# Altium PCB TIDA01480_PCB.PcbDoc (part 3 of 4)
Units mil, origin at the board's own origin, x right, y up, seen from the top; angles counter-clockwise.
Board outline 2500 x 3500 mil, 6 copper layers (Top Layer, GND Upper, Signal Layer 1, Signal Layer 2, GND Lower, Bottom Layer), stack 63.4 mil thick; 332 components, 140 nets, 983 pads, 692 vias.
Unrouted connection lines stored in the file: 17.
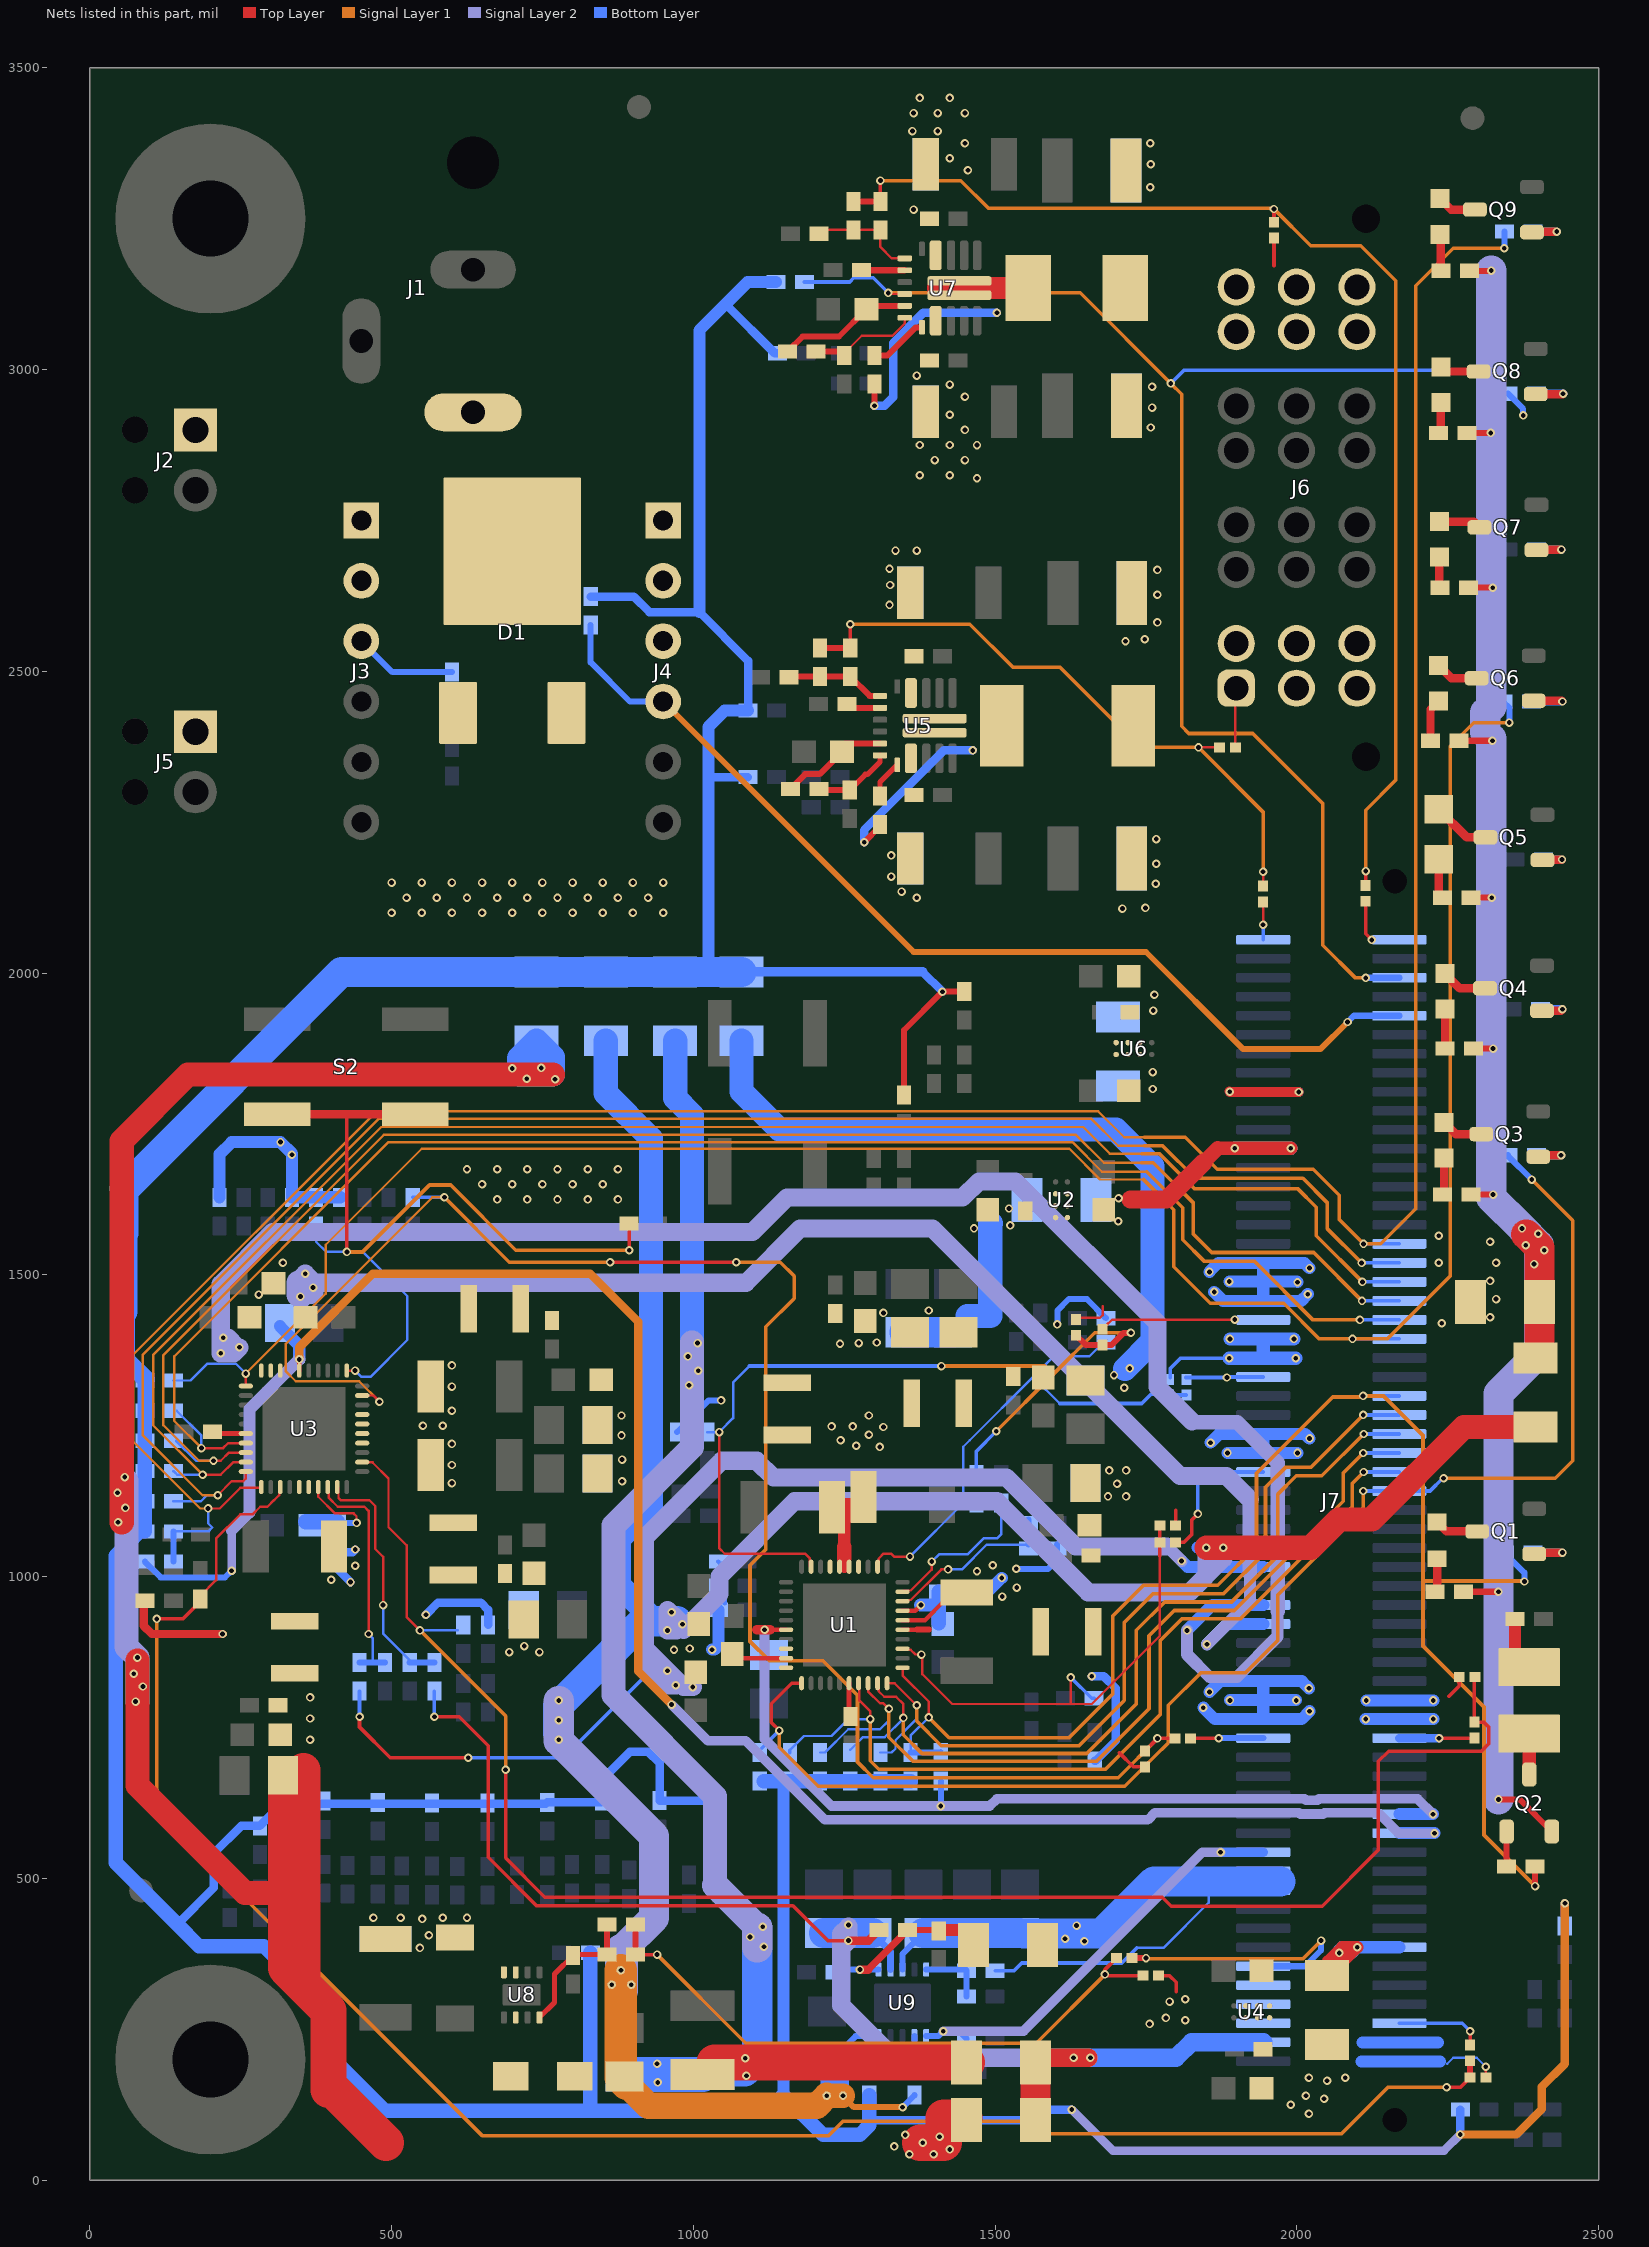
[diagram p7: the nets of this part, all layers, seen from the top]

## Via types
v1: diameter 14, hole 7.9, Top Layer to Bottom Layer, tented both sides, 676 vias
v2: diameter 19.68, hole 7.87, Top Layer to Bottom Layer, 16 vias

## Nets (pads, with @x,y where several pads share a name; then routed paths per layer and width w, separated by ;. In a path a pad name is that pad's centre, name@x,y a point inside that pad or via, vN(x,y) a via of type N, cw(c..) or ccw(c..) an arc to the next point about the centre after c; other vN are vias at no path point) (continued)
HOT_RESETz_B: R29.1 R38.1 S2.3 S2.4 U3.11 | length 1475
  Top Layer w4: U3.11@425.87,1341.46 v1(439.54,1341.46)
  Top Layer w6: v1(426,1538) 426,1765.26 ; v1(894,1541) R29.1@894,1584.38
  Top Layer w14: S2.3@310.83,1766.26 S2.4@539.17,1766.26
  Signal Layer 1 w6: v1(426,1538) 452,1538 563,1649 598,1649 706,1541 v1(894,1541)
  Bottom Layer w4: R38.1@375,1581.38 375,1555 392,1538 v1(426,1538) 453,1538 526,1465 526,1392.14 464.86,1331 450,1331 v1(439.54,1341.46)
HV_AIC_PG: J4.4 J7.112 R156.2 | length 1689.6
  Signal Layer 1 w10: J4.4@950,2450 1365,2035 1750,2035 1911,1874 2039,1874 v1(2084,1919)
  Bottom Layer w10: R156.2@829.92,2576.38 829.92,2515 894.92,2450 J4.4@950,2450 ; v1(2084,1919) 2094.33,1929.33 J7.112@2169.74,1929.33
I2C_CLK_A: J7.70 R3.1 U1.30 | length 1386.1
  Top Layer w4: U1.30@1321.08,823.54 1333.46,823.54 v1(1370,787)
  Signal Layer 1 w6: v1(1370,787) 1370,761 1411,720 1639,720 1714,795 1714,924 1762,972 1879,972 1948,1041 1948,1148 1981,1181 2023.17,1181 v1(2110.09,1267.91)
  Bottom Layer w4: R3.1@1310,708.62 1328.62,708.62 1335,715 1335,729 1370,764 v1(1370,787)
  Bottom Layer w6: v1(2110.09,1267.91) J7.70@2169.74,1267.91
I2C_CLK_B: J7.86 R31.1 U3.30 | length 2813.2
  Top Layer w4: v1(212,1135) 235,1158 254,1158 258.54,1162.54 U3.30@258.54,1174.13
  Signal Layer 1 w4: v1(212,1135) 187,1135 88,1234 88,1368 479,1759 1659,1759 1704,1714 1747,1714
  Signal Layer 1 w6: 1747,1714 1777.38,1714 1831.38,1660 2010,1660 2050,1620 2050,1577 v1(2107.12,1519.88)
  Bottom Layer w4: R31.1@138.62,1125 184.14,1125 193.57,1134.43 v1@211.43,1134.43
  Bottom Layer w6: v1(2107.12,1519.88) J7.86@2169.74,1519.88
I2C_DAT_A: J7.68 R4.1 U1.29 | length 1409.2
  Top Layer w4: U1.29@1305.33,823.54 1307,821.88 1307,810.22 1316.22,801 1336,801 1348,789 v1(1348,766)
  Signal Layer 1 w6: v1(1348,766) 1348,738 1379,707 1652,707 1734,789 1734,911 1781,958 1891.62,958 1968,1034.38 1968,1136 1999,1167 2041.17,1167 v1(2110.58,1236.42)
  Bottom Layer w4: R4.1@1260,713 1281.24,734.24 1317.24,734.24 v1@1348,765
  Bottom Layer w6: v1(2110.58,1236.42) J7.68@2169.74,1236.42
I2C_DAT_B: J7.84 R32.1 U3.29 | length 2717.3
  Top Layer w4: v1(187,1169) 217,1169 237.88,1189.88 U3.29@258.54,1189.88
  Signal Layer 1 w4: v1(187,1169) 105,1251 105,1367 483,1745 1646,1745 1690,1701 1743,1701
  Signal Layer 1 w6: 1743,1701 1772,1701 1830,1643 2001,1643 2032,1612 2032,1565 v1(2108.61,1488.39)
  Bottom Layer w4: R32.1@138.62,1175 R32.1@142.62,1171 ; R32.1@144.62,1169 v1(187,1169) v1@187,1171
  Bottom Layer w6: v1(2108.61,1488.39) J7.84@2169.74,1488.39
INTERRUPTz_A: J7.66 R14.1 U1.28 | length 1433.5
  Top Layer w4: U1.28@1289.59,823.54 1289.59,810 1309.59,790 1315,790 v1(1324,781)
  Signal Layer 1 w6: v1(1324,781) 1324,734 1364,694 1668,694 1755,781 1755,902 1797,944 1896,944 2077,1125 2077,1171.84 v1(2110.08,1204.92)
  Bottom Layer w4: R14.1@1210,708.62 1218.28,708.62 1256.78,747.13 1309.13,747.13 1324,762 v1@1324,780.13
  Bottom Layer w6: v1(2110.08,1204.92) J7.66@2169.74,1204.92
INTERRUPTz_B: J7.82 R47.1 U3.28 | length 2701.6
  Top Layer w4: v1(205,1192) 217,1192 230.63,1205.63 U3.28@258.54,1205.63
  Signal Layer 1 w4: v1(205,1192) 181,1192 122,1251 122,1367 487,1732 1634,1732 1680,1686 1742,1686
  Signal Layer 1 w6: 1742,1686 1762,1686 1828,1620 1828,1568 1859,1537 2027.78,1537 v1(2107.89,1456.89)
  Bottom Layer w4: R47.1@143,1225 176,1192 v1(205,1192)
  Bottom Layer w6: v1(2107.89,1456.89) J7.82@2169.74,1456.89
LDO1B__or__VPS_MTRAVTT: C48.1 J7.49 U3.20 | length 2925
  Signal Layer 2 w20: v1(1818,911) 1818,871 1855,834 1901,834 1968,901 1968,943
  Signal Layer 2 w24: 1826,1257 1826.87,1256.13 1900.87,1256.13 1968,1189 1968,943
  Signal Layer 2 w30: v1(221,1396) 229,1396 245,1380 v1(248,1380) 238,1370 v1(217,1370) 217,1485 302.87,1570.87 1097.87,1570.87 1155,1628 1446,1628 1473,1655 1534,1655 1769,1420 1769,1314 1826,1257
  Bottom Layer w20: v1(1818,911) 1859.95,952.95 J7.49@1944.26,952.95
LDO2B: C49.1 J7.47 U3.18 | length 2266
  Signal Layer 2 w20: v1(1851,888) 1922,959 1922,1005
  Signal Layer 2 w24: 1922,1005 1922,1128
  Signal Layer 2 w30: 346,1491 v1(357,1502) 372,1487 ; 352,1487 372,1487 ; 386,1487 372,1487 ; 1922,1128 1883.13,1166.87 1806.13,1166.87 1396,1577 1177,1577 1087,1487 372,1487
  Signal Layer 2 w40: 346,1487 346,1467 v1(349,1464) ; 352,1487 367,1472
  Bottom Layer w20: v1(1851,888) 1884.46,921.46 J7.47@1944.26,921.46
  other v1: 370,1479
LOW_BATz_A: J7.62 R12.1 R125.1 U1.21 | length 2406
  Top Layer w6: v1@1143,744.5 1129,758.5 1129,789.41 1163.13,823.54 U1.21@1179.35,823.54
  Signal Layer 1 w6: v1(1142.5,745) 1142.5,717.5 1207,653 1715,653 1776.13,714.13 1776.41,714.13 1786.88,724.6 1786.88,786.88 1841,841 1915,841 1968,894 1968,969 2110.07,1111.07 v1(2110.07,1141.93) ; v1(2243,1163) 2428,1163 2457,1192 2457,1590 v1(2389,1658)
  Bottom Layer w6: R12.1@1110,708.62 1110,712.5 v1(1142.5,745) ; v1(2110.07,1141.93) J7.62@2169.74,1141.93 2220.64,1141.93 2241.72,1163 v1(2243,1163)
  Bottom Layer w10: R125.1@2350.14,1698.21 2350.14,1696.86 v1(2389,1658)
LOW_BATz_B: J7.78 R45.1 R128.1 U3.21 | length 3694.4
  Top Layer w4: U3.21@258.54,1315.87 v1(258.54,1336.46)
  Signal Layer 1 w4: v1(258.54,1336.46) 391,1468.91 391,1550 550,1709 1623,1709 1674,1658 1746,1658
  Signal Layer 1 w6: 1746,1658 1796,1608 1796,1513.49 1856.49,1453 1978,1453 2037.1,1393.9 v1(2092.1,1393.9) 2149.9,1393.9 2254,1498 2254,2376 2293,2415 v1(2352,2415)
  Bottom Layer w4: R45.1@138.62,1325 167.14,1325 195.14,1353 242,1353 v1(258.54,1336.46)
  Bottom Layer w6: v1(2092.1,1393.9) J7.78@2169.74,1393.9
  Bottom Layer w10: R128.1@2341.38,2450 2352,2439.38 v1(2352,2415)
LOWBAT_SNS_A: R7.1 R9.2 U1.39 | length 303.7
  Top Layer w4: U1.39@1346.67,975.12 1348.61,977.05 1360.27,977.05 1395,1011.79 v1(1395,1025)
  Bottom Layer w4: v1(1395,1025) 1407,1037 1454.44,1037 1481.44,1064 1504,1064 1510,1070 R9.2@1510,1122.38
  Bottom Layer w10: R7.1@1469,1122.38 R9.2@1510,1122.38
LOWBAT_SNS_B: R34.1 R35.2 U3.39 | length 405.1
  Top Layer w4: U3.39@410.12,1148.54 412.06,1146.61 412.06,1130.34 415.53,1126.86 463.14,1126.86 473,1117 473,1046 486,1033 v1(486,953)
  Bottom Layer w4: v1(486,953) 486,906 R35.2@530,862
  Bottom Layer w10: R35.2@530,857.62 R34.1@571,857.62
MidCurrent_PG: J7.116 R72.2 R133.1 U7.16 | length 2591.6
  Top Layer w4: v1@1320,3130 v1(1323,3127) 1324.84,3125.16 U7.16@1350.26,3125.16
  Signal Layer 1 w6: v1(1323,3127) 1641,3127 v1(1791,2977) 1809,2959 1809,2409 1821,2397 1927,2397 2043,2281 2043,2046 2097,1992 v1(2114,1992)
  Bottom Layer w6: R72.2@1183.84,3145 1259,3145 1265.87,3151.87 1298.13,3151.87 v1(1323,3127) ; v1(1791,2977) 1813,2999 2307,2999 2346,2960 R133.1@2350,2960
  Bottom Layer w10: v1@2114.32,1992.32 J7.116@2169.74,1992.32 ; R133.1@2350,2960 2375,2935 v1(2375,2924)
NetC7_1: C7.1 R1.2 U1.37 | length 113.7
  Top Layer w7: U1.37@1346.67,943.62 1367.62,943.62 v1(1377,953)
  Bottom Layer w22: v1(1377,953) 1404.4,953
  Bottom Layer w24: C7.1@1406.38,922.87 R1.2@1406.38,975
NetC22_1: C22.1 U1.26 | length 52.8
  Top Layer w7.8: C22.1@1258.09,770.75 U1.26@1258.09,823.54
NetC32_1: C32.1 R30.2 U3.37 | length 177.4
  Top Layer w4: U3.37@378.62,1148.54 378.62,1132.47 406.23,1104.86 437.14,1104.86 442,1100 v1(442,1089)
  Bottom Layer w10: R30.2@420,1089 v1(442,1089)
  Bottom Layer w26: C32.1@358,1091 R30.2@409.51,1091
NetC47_1: C47.1 U3.26 | length 52
  Top Layer w7.8: C47.1@206.5,1237.13 U3.26@258.54,1237.13
NetC51_1: C51.1 U5.1 | length 63.3
  Top Layer w9: C51.1@1309.27,2293.62 1309.27,2316.46 U5.1@1337.85,2345.04
NetC51_2: C51.2 L7.1 U5.6 U5.7 | length 291.8
  Top Layer w10: v1(1283,2217) C51.2@1309.27,2243.27
  Bottom Layer w14: v1(1283,2217) 1283,2237 1415,2369 v1(1463,2369)
NetC62_2: C62.2 R61.1 R63.2 U5.13 | length 162.6
  Top Layer w10: R63.2@1160,2491.38 C62.2@1210,2491.38 R61.1@1260,2491.38 1292.17,2459.21 U5.13@1309.31,2459.21
NetC67_1: C67.1 U5.14 | length 41.2
  Top Layer w10: C67.1@1268.15,2439.53 U5.14@1309.31,2439.53
NetC68_1: C68.1 U7.1 | length 97.9
  Top Layer w10: C68.1@1300,3023.62 1321.88,3023.62 1368.29,3070.04 U7.1@1378.72,3070.04
NetC68_2: C68.2 L8.1 U7.6 U7.7 | length 505.7
  Top Layer w10: v1(1300,2940) C68.2@1300,2976.38
  Top Layer w36: 1405,3135 L8.1@1554.78,3135
  Bottom Layer w14: v1(1300,2940) 1317,2940 1331,2954 1331,3044 1381,3094 v1(1503,3094)
NetC79_2: C79.2 R73.1 R74.2 U7.13 | length 171.4
  Top Layer w4: R74.2@1215,3231.38 C79.2@1265.22,3231.38 R73.1@1310,3231.38 1310,3203 1328.79,3184.21 U7.13@1350.26,3184.21
NetC81_1: C81.1 U7.14 | length 70.9
  Top Layer w10: C81.1@1279.31,3164.53 U7.14@1350.26,3164.53
NetC93_2: C93.2 R83.2 R86.2 U8.4 | length 232.8
  Top Layer w8: U8.4@745.16,269.69 770,294.53 770,341.71 R86.2@800.79,372.5 802.17,373.87 R83.2@857.17,373.87
  Top Layer w10: R83.2@857.17,373.87 C93.2@857.17,423.87
NetC94_1: C94.1 R81.1 U9.5 | length 108.1
  Bottom Layer w10: U9.5@1385.85,349.02 R81.1@1451.1,349.02 ; C94.1@1452.85,304.45 R81.1@1452.85,347.26
NetD1_1: D1.1 D1.3 J4.1 J4.2 J4.3
NetD2_1: D2.1 Q1.3 | length 72.8
  Top Layer w14: D2.1@2232.4,1090.51 2247.91,1075 Q1.3@2298.74,1075
NetD2_2: D2.2 R117.1 | length 50.9
  Top Layer w14: R117.1@2232.4,978.62 D2.2@2232.4,1029.49
NetD3_1: D3.1 Q2.3 | length 67.6
  Top Layer w23: Q2.3@2385,672.24 D3.1@2385,739.88
NetD3_2: D3.2 R118.2 | length 56.3
  Top Layer w20: D3.2@2361.38,873.74 R118.2@2361.38,930
NetD4_1: D4.1 R119.1 | length 58.3
  Top Layer w14: R119.1@2243.76,1635.38 D4.1@2243.76,1693.68
NetD4_2: D4.2 Q3.3 | length 69.7
  Top Layer w14: D4.2@2243.76,1752.74 2263.29,1733.21 Q3.3@2305.41,1733.21
NetD5_1: D5.1 R120.1 | length 65.1
  Top Layer w14: R120.1@2245.38,1875 D5.1@2245.38,1940.09
NetD5_2: D5.2 Q4.3 | length 76.8
  Top Layer w14: D5.2@2245,1999.53 2269.53,1975 Q4.3@2311.65,1975
NetD6_1: D6.1 R121.1 | length 57.3
  Top Layer w14: R121.1@2235,2131.38 D6.1@2235,2188.66
NetD6_2: D6.2 Q5.3 | length 96.6
  Top Layer w14: D6.2@2235,2271.34 2281.34,2225 Q5.3@2312.44,2225
NetD7_1: D7.1 R122.1 | length 71.1
  Top Layer w14: R122.1@2221.38,2385 2221.38,2436.85 D7.1@2235,2450.47
NetD7_2: D7.2 Q6.3 | length 71.4
  Top Layer w14: D7.2@2235,2509.53 2255.93,2488.6 Q6.3@2297.76,2488.6
NetD8_1: D8.1 R129.1 | length 49.1
  Top Layer w14: R129.1@2236.04,2639.96 D8.1@2236.04,2689.05
NetD8_2: D8.2 Q7.3 | length 70.4
  Top Layer w14: D8.2@2236.04,2748.11 2292.97,2748.11 Q7.3@2302.5,2738.58
NetD9_1: D9.1 R130.1 | length 46.9
  Top Layer w14: R130.1@2238.62,2898.62 D9.1@2238.62,2945.47
NetD9_2: D9.2 Q8.3 | length 65.6
  Top Layer w14: D9.2@2238.62,3004.53 2246.36,2996.79 Q8.3@2301.06,2996.79
NetD10_1: D10.1 R131.1 | length 59.1
  Top Layer w14: R131.1@2238.62,3163.52 D10.1@2238.62,3222.62
NetD10_2: D10.2 Q9.3 | length 65.2
  Top Layer w14: D10.2@2237.24,3283.05 2255.3,3265 Q9.3@2295,3265
NetJ3_1: J3.1 J3.2 J3.3 J5.1 R155.1 | length 171.3
  Bottom Layer w10: J3.3@450,2550 501.38,2498.62 R155.1@600,2498.62
NetJ7_6: J7.6 R153.1 | length 145.7
  Top Layer w6: R153.1@2287,223.99 v1(2287,247)
  Bottom Layer w6: J7.6@2169.74,260.04 2273.96,260.04 v1(2287,247)
NetJ7_11: J7.11 R151.2 | length 447.2
  Top Layer w10: R151.2@1726.99,368 v1(1750,368)
  Signal Layer 1 w6: v1@1750.87,367.13 2010.13,367.13 v1(2040,397)
  Bottom Layer w10: J7.11@1944.26,354.53 2013.53,354.53 2040,381 v1(2040,397)
NetJ7_35: J7.35 R148.2 | length 119.8
  Top Layer w6: R148.2@1824.47,732.48 v1(1870.52,732.48)
  Bottom Layer w10: v1(1870.52,732.48) J7.35@1944.26,732.48
NetJ7_36: J7.36 R149.1 | length 123.7
  Top Layer w6: v1(2235.52,732.48) R149.1@2293.47,732.48
  Bottom Layer w14: J7.36@2169.74,732.48 v1(2235.52,732.48)
NetJ7_63: J7.63 R144.2 | length 238.7
  Top Layer w6: R144.2@1798.99,1057 1813,1057 1825.92,1069.92 1825.92,1093.92 v1(1836,1104)
  Bottom Layer w6: v1(1836,1104) 1836,1157.25 1852.18,1173.43 J7.63@1944.26,1173.43
NetJ7_73: J7.73 R142.2 | length 127.4
  Bottom Layer w6: R142.2@1815.99,1330 v1(1884,1330) ; v1@1884.91,1330.91 J7.73@1944.26,1330.91
NetJ7_79: J7.79 R140.2 | length 217.1
  Top Layer w4: R140.2@1684.01,1416 1694.01,1426 v1(1897,1426)
NetJ7_119: J7.119 R137.2 | length 62.4
  Top Layer w4: v1(1944,2080) R137.2@1944,2118.01
  Bottom Layer w6: J7.119@1944,2055.58 v1(1944,2080)
NetJ7_120: J7.120 R138.1 | length 68.2
  Top Layer w6: R138.1@2114,2119.01 2114,2065 v1(2124,2055)
NetL1_1: L1.1 U1.7
NetL2_1: L2.1 U1.35 | length 43.4
  Top Layer w7: U1.35@1346.67,912.13 1370.87,912.13
  Top Layer w10: 1370.87,912.13 1390.05,912.13
NetL3_1: L3.1 U1.4
NetL4_1: L4.1 U3.7
NetL5_1: L5.1 U3.35
NetL6_1: L6.1 U3.4
NetL9_1: L9.1 U8.2
NetQ1_1: Q1.1 R123.2 | length 96.7
  Top Layer w14: Q1.1@2393.23,1037.6 2395.63,1040 v1(2440,1040)
  Bottom Layer w14: R123.2@2391.02,1040 v1(2440,1040)
NetQ2_1: Q2.1 R124.2 | length 57.5
  Top Layer w10: R124.2@2347.38,520 Q2.1@2347.38,577.54
NetQ3_1: Q3.1 R125.2 | length 79.3
  Top Layer w14: Q3.1@2399.9,1695.81 2402.3,1698.21 v1(2437.79,1698.21)
  Bottom Layer w14: R125.2@2397.38,1698.21 v1(2437.79,1698.21)
NetQ4_1: Q4.1 R126.2 | length 71.2
  Top Layer w14: Q4.1@2406.14,1937.6 2437.6,1937.6 v1(2440,1940)
  Bottom Layer w14: R126.2@2403.62,1940 v1(2440,1940)
NetQ5_1: Q5.1 R127.2 | length 63.1
  Top Layer w14: Q5.1@2406.93,2187.6 2438.6,2187.6 v1(2439.21,2188.21)
  Bottom Layer w14: R127.2@2408.62,2188.21 v1(2439.21,2188.21)
NetQ6_1: Q6.1 R128.2 | length 99.6
  Top Layer w14: Q6.1@2392.24,2451.2 2438.8,2451.2 v1(2440,2450)
  Bottom Layer w14: R128.2@2388.62,2450 v1(2440,2450)
NetQ7_1: Q7.1 R132.2 | length 81.4
  Top Layer w14: Q7.1@2396.99,2701.18 v1@2437.6,2701.18
  Bottom Layer w14: R132.2@2397.38,2701.79 v1(2438.21,2701.79)
NetQ8_1: Q8.1 R133.2 | length 88.6
  Top Layer w14: Q8.1@2395.55,2959.39 v1@2440.39,2959.39
  Bottom Layer w14: R133.2@2397.24,2960 v1(2441,2960)
NetQ9_1: Q9.1 R134.2 | length 79.8
  Top Layer w14: Q9.1@2390.41,3228.52 v1(2430.52,3228.52)
  Bottom Layer w14: R134.2@2390.87,3228.52 v1(2430.52,3228.52)
NetR64_1: R64.1 R65.2 U5.18 | length 129.9
  Top Layer w9: R65.2@1259.27,2303.62 1284.86,2329.21 1288.37,2329.21 1309.31,2350.16 U5.18@1309.31,2360.79
  Top Layer w10: R64.1@1209.27,2303.62 R65.2@1259.27,2303.62
NetR75_1: R75.1 R76.2 U7.18 | length 170.2
  Top Layer w4: R76.2@1250,3027 1279,3056 1330,3056 1350.26,3076.26 U7.18@1350.26,3085.79
  Top Layer w10: R75.1@1203.62,3030 R76.2@1243.62,3030
NetR80_2: R80.2 R85.1 U9.7 | length 110.3
  Bottom Layer w10: R80.2@1366.16,188.39 U9.7@1366.16,238.78 ; R80.2@1366.48,188.07 1375.1,179.45 R85.1@1422.85,179.45
PWRFAIL_SNS_A: R21.1 R26.2 U1.38 | length 289.5
  Top Layer w4: U1.38@1346.67,959.37 1348.61,961.31 1360.27,961.31 1410.96,1012 v1(1422,1012)
  Bottom Layer w4: v1(1422,1012) 1445,1012 1486,1053 R21.1@1555.38,1053
  Bottom Layer w10: R21.1@1555.38,1053 R26.2@1555.38,1095
PWRFAIL_SNS_B: R40.1 R42.2 U3.38 | length 388.4
  Top Layer w4: U3.38@394.37,1148.54 396.31,1146.61 396.31,1130.34 410.79,1115.86 410.88,1115.95 410.98,1115.86 455.14,1115.86 462,1109 v1(462,905)
  Bottom Layer w4: v1(462,905) 468.65,898.35 468.65,858.93
  Bottom Layer w10: R40.1@447,857.62 R42.2@489,857.62
PWRFAILz_A: J7.72 R10.2 R11.1 R123.1 R124.1 U1.31 | length 2613.7
  Top Layer w4: U1.31@1346.67,849.13 1346.67,836.33 1390,793 v1(1390,766.75)
  Top Layer w10: v1(2394.62,487.38) R124.1@2394.62,520
  Signal Layer 1 w6: v1(1390,766.75) 1423.75,733 1622.41,733 1695,805.59 1695,935 1746,986 1869,986 1933,1050 1933,1171.28 2059.31,1297.59 2109.59,1297.59 v1(2109.59,1299.41) 2143.59,1299.41 2209,1234 2209,885 2310,784 2310,572 v1(2394.62,487.38) ; 2209.13,992.87 2376.13,992.87 v1(2377,992)
  Bottom Layer w4: R11.1@1360,708.62 1360,736.75 v1(1390,766.75) ; R10.2@1410,708.62 R10.2@1410,712.56
  Bottom Layer w6: v1(2109.59,1299.41) J7.72@2169.74,1299.41
  Bottom Layer w10: R11.1@1360,708.62 R10.2@1410,708.62 ; R123.1@2343.78,1040 2377,1006.78 v1(2377,992)
PWRFAILz_B: J7.88 R43.2 R44.1 R134.1 U3.31 | length 4788.5
  Top Layer w4: v1(196,1113) 215.44,1113 249.44,1147 284.13,1147 U3.31@284.13,1148.54
  Signal Layer 1 w4: v1(196,1113) 183,1113 72,1224 72,1368 475,1771 1671,1771 1714,1728 1747,1728
  Signal Layer 1 w6: 1747,1728 1815,1728 1868,1675 2027,1675 2070,1632 2070,1591.76 v1(2110.38,1551.38) 2139,1551.38 2197,1609.38 2197,3139 2259,3201 v1(2343.62,3201)
  Bottom Layer w4: R44.1@138.62,1075 196.46,1075 203,1081.54 196,1088.54 v1(196,1113)
  Bottom Layer w6: v1(2110.38,1551.38) J7.88@2169.74,1551.38
  Bottom Layer w10: R43.2@138.62,1025 R44.1@138.62,1075 ; v1(2343.62,3201) R134.1@2343.62,3228.52
RESETz_A: J7.64 R13.1 U1.27 | length 1476
  Top Layer w4: U1.27@1274.78,822.61 1274.78,795.59 1293,777.36 v1(1293,764)
  Top Layer w6: U1.27@1273.84,823.54 U1.27@1274.78,822.61
  Signal Layer 1 w6: v1(1293,764) 1293,695 1307,681 1683,681 1773.88,771.88 1773.88,894.88 1809,930 1906,930 2092,1116 2092,1154.85 v1(2110.57,1173.43)
  Bottom Layer w4: R13.1@1160,712.56 1183.44,736 1228.86,736 1256.86,764 v1(1293,764)
  Bottom Layer w6: R13.1@1160,708.62 R13.1@1160,712.56 ; v1(2110.57,1173.43) J7.64@2169.74,1173.43
RESETz_B: J7.80 R46.1 U3.27 | length 2656.7
  Top Layer w4: v1(185,1213) 221,1213 229.38,1221.38 U3.27@258.54,1221.38
  Signal Layer 1 w4: v1(185,1213) 140,1258 140,1365 495,1720 1628,1720 1677,1671 1751.38,1671
  Signal Layer 1 w6: 1751.38,1671 1811,1611.38 1811,1558 1846.13,1522.87 1929.13,1522.87 2026.61,1425.39 v1(2104.39,1425.39)
  Bottom Layer w4: R46.1@144,1275 185,1234 v1(185,1213)
  Bottom Layer w6: v1(2104.39,1425.39) J7.80@2169.74,1425.39
VCC_1or2A: C88.1 C89.1 C90.1 C91.1 C93.1 J7.5 J7.7 J7.9 L9.2 R66.2 R71.2 R83.1 R151.1 R152.1 R152.2 | length 3681.2
  Top Layer w6: R83.1@904.41,373.87 v1(939.9,373.87) ; v1(1682,341) 1682,348.99 R151.1@1701.01,368 ; v1@1684,339 R152.2@1745.01,339 R152.2@1743.01,341 ; R152.1@1770.99,339 1789,339 1800,328 1800,312
  Top Layer w10: R83.1@904.41,373.87 C93.1@904.41,423.87
  Top Layer w60: C90.1@1035,195 R66.2@1452.91,195
  Signal Layer 1 w6: v1(939.9,373.87) 1086.77,227 1568,227 v1(1682,341)
  Signal Layer 2 w40: 998,1388 998,1215 868,1085 868,804 1036,636 1036,489
  Signal Layer 2 w44: 1036,489 1106,419
  Signal Layer 2 w50: 1106,386 1106,419
  Bottom Layer w40: R71.2@970,1887.91 970,1793 998,1765 998,1324
  Bottom Layer w50: C91.1@1012.09,172.09 C91.1@1015,175 1020,180 1085.17,180 1106,200.83 1106,418
  Bottom Layer w58: C89.1@888.54,175 C91.1@1015,175
  other v1: 941,162 1088,173 940,193 1086,202 1756,259 1815,265 1783,269 1789,296 1815,300 1117,387 1094,403 1115,420 993,1317 1008,1341 991,1365 1007,1387
VCC_8A: C75.1 C76.1 C77.1 C78.1 C79.1 J6.4 L8.2 R73.2 R138.2 R150.1 R150.2 | length 2093.7
  Top Layer w6: R73.2@1310,3278.62 v1(1310,3313) ; 1961.99,3171.99 R150.1@1961.99,3219 ; R150.2@1962,3243.99 v1(1962,3266) ; R138.2@2114,2144.99 v1(2114,2169)
  Top Layer w10: C79.1@1265.22,3278.62 R73.2@1310,3278.62
  Signal Layer 1 w6: v1(1310,3313) 1443,3313 1489,3267 1961,3267 v1(1962,3266) 2023,3205 2106,3205 2164,3147 2164,2320 2114,2270 v1(2114,2169)
  other v1: 1758,2904 1760,2937 1760,2971.35 1757,3302 1758,3340 1757,3375
VCC_12A: C58.1 C59.1 C60.1 C61.1 C62.1 C64.1 C65.1 J6.1 L7.2 R61.2 R62.1 R137.1 R145.1 R145.2 U6.A2 U6.B2 U6.C2 | length 1155.7
  Top Layer w4: v1(1837,2374) R145.2@1872.01,2374 ; R145.1@1897.99,2374 J6.1@1897.99,2470.52 ; R137.1@1944,2143.99 v1(1944,2168)
  Top Layer w6: R61.2@1260,2538.62 v1@1260,2577
  Top Layer w10: C62.1@1210,2538.62 R61.2@1260,2538.62
  Signal Layer 1 w6: v1(1260,2578) 1458,2578 1529,2507 1607,2507 1740,2374 v1(1837,2374) 1944,2267 v1(1944,2168)
  other v1: 1762,1938 1764,1964 1711,2107 1749,2108 1766,2148 1767,2181 1767,2222 1716,2550 1748,2553 1769,2581 1769,2627 1769,2668
VCC_12A_LS3: C66.1 J7.103 R62.2 U6.A1 U6.B1 U6.C1 | length 229.4
  Top Layer w16: v1@1888,1804 1889,1803 v1(2003,1803)
  Bottom Layer w16: v1(1888.65,1803.35) J7.103@1944.26,1803.35 ; J7.103@1944.61,1803 v1(2003,1803)
  other v1: 1761,1808 1761,1836
VCC_PSPLL: C11.1 J7.97 R2.2 U2.A1 U2.B1 U2.C1 | length 394.2
  Top Layer w22: 1869,1710 v1(1897,1710) v1(1990,1710)
  Top Layer w24: 1845,1686 1869,1710
  Top Layer w30: 1724,1625 1784,1625 1845,1686
  Bottom Layer w22: v1(1897,1710) v1(1990,1710)
  other v1: 1704,1589 1704.49,1627
VDCDC1_A: C1.1 C2.1 C3.1 C4.1 C5.1 C6.1 C9.1 C10.1 J7.81 J7.83 J7.85 L1.2 R2.1 R7.2 R15.2 R139.1 R139.2 R140.1 U1.9 U2.A2 U2.B2 U2.C2 | length 2355.3
  Top Layer w4: v1@1043.13,1239.5 1043.13,1046.95 1052.08,1038 1168,1038 1168.14,1038.14 1185.07,1038.14 1193.16,1030.05 1193.16,1018.39 U1.9@1195.1,1016.46 ; R139.2@1634,1425.99 1636.93,1428.92 1673.78,1428.92 1678,1433.14 1678,1448
  Top Layer w10: R139.1@1634,1400.01 1650,1384.01 R140.1@1678,1384.01 1693.01,1384.01 1713,1404 v1(1725,1404)
  Signal Layer 1 w6: v1(1411,1349) 1582,1349 1596,1335 ; v1(1502,1241) 1596,1335 ; v1(1725,1404) 1665,1404 1596,1335
  Bottom Layer w4: R15.2@1023,1239.62 v1(1043,1239.62) 1066,1262.62 1066,1322 1093,1349
  Bottom Layer w6: 1093,1349 v1(1411,1349) ; R7.2@1469,1169.62 1469,1208 v1(1502,1241)
  Bottom Layer w20: v1(1855,1505) 1869.88,1519.88 J7.85@1944.26,1519.88 ; v1(1863,1471.76) 1877.88,1456.89 J7.81@1944.26,1456.89 ; v1(1888,1489) J7.83@1944.26,1489 ; v1(2001,1488) 2000,1489 J7.83@1944.26,1489 ; v1(2018,1468) 2006.89,1456.89 J7.81@1944.26,1456.89 ; v1(2020.93,1511.23) 2012.28,1519.88 J7.85@1944.26,1519.88 ; J7.81@1944.26,1456.89 J7.83@1944.26,1488.39 J7.83@1944.26,1489 ; J7.83@1944.26,1489 J7.85@1944.26,1519.88
  Bottom Layer w40: 1454,1432.13 1491.87,1432.13 1491.87,1583.87 1493,1585
  Bottom Layer w50: C6.1@1350,1405 C4.1@1430,1405
  other v1: 1243,1386 1274,1387 1304,1388 1315,1437 1390,1441 1465,1577 1525,1582 1523,1610
VDCDC1_B: C26.1 C27.1 C28.1 C29.1 C30.1 C31.1 J7.37 J7.39 J7.41 L4.2 R48.2 R146.1 R146.2 R148.1 U3.9 | length 3448.4
  Top Layer w4: U3.9@451.46,1300.12 470.12,1300.12 470.12,1299.88 v1(480,1290)
  Top Layer w6: v1(862,1521) v1(1071,1521) ; 1706,708 1728.99,685.01 R146.1@1748,685.01 ; R146.2@1748,710.99 v1(1769.01,732) R148.1@1798.01,732
  Signal Layer 1 w4: v1(480,1290) 446.23,1323.77 341.23,1323.77 325,1340 325,1386 567.62,1628.62 v1(587.62,1628.62)
  Signal Layer 1 w6: v1(587.62,1628.62) 695.24,1521 v1(862,1521) ; v1(1071,1521) 1144,1521 1167,1498 1167,1461 1120,1414 1120,1045 1094,1019 1094,892.62 1125.62,861 1214.38,861 1272.03,803.36 1272.03,692.97 1298,667 1704.01,667 v1(1769.01,732)
  Bottom Layer w6: R48.2@535,1628.62 v1(587.62,1628.62)
  Bottom Layer w20: v1(1845,783) 1864.02,763.98 J7.37@1944.26,763.98 ; v1(1855,809) 1872.97,826.97 J7.41@1944.26,826.97 ; v1@1889.47,795.47 J7.39@1944.26,795.47 ; v1@1998.53,795.47 J7.39@1944.26,795.47 ; v1(2020,815) 2008.03,826.97 J7.41@1944.26,826.97 ; v1(2021,777) 2007.98,763.98 J7.37@1944.26,763.98 ; J7.37@1944.26,763.98 J7.39@1944.26,795.47 ; J7.39@1944.26,795.47 J7.41@1944.26,826.97
  other v1: 1889,795 1999,795 882,1158 882,1194 881,1234 881,1267
VDCDC2_A: C14.1 C15.1 C16.1 C17.1 J7.65 J7.67 L2.2 R16.2 R143.1 R143.2 R144.1 U1.33 | length 1154.3
  Top Layer w4: U1.33@1346.67,880.63 1348.61,878.69 1360.27,878.69 1367.96,871 v1(1378,871) 1379.36,869.64 1379.36,838.64 1429,789 1660,789 1773.01,902.01 1773.01,1034.01 ; 1625.34,789.34 v1(1625.34,833)
  Top Layer w6: 1773.01,1034.01 R144.1@1773.01,1057 R143.1@1773.01,1085 ; R143.2@1798.99,1085 1798.99,1109.99
  Bottom Layer w6: v1(1625.34,833) 1659.96,798.38 R16.2@1663.84,798.38
  Bottom Layer w20: v1(1857,1222) 1871.42,1236.42 J7.67@1944.26,1236.42 ; v1(1885,1205) J7.65@1944.26,1205 ; J7.65@1944.26,1204.92 J7.65@1944.26,1205 ; v1(2001,1205) J7.65@1944.26,1205 ; v1(2021,1229) 2013.58,1236.42 J7.67@1944.26,1236.42 ; J7.65@1944.26,1205 J7.67@1944.26,1236.42
  other v1: 1687,1133 1717,1133 1702,1154 1689,1176 1717,1176
VDCDC2_B: C36.1 C37.1 C38.1 C39.1 C40.1 C41.1 J7.2 J7.4 L5.2 R33.1 R49.2 R67.2 R69.2 R153.2 R154.1 R154.2 U3.33 U4.A2 U4.B2 U4.C2 | length 7179
  Top Layer w4: R49.2@183,968 209.24,994.24 209.24,1063.13 249.3,1103.18 269.88,1103.18 282.56,1115.86 294.41,1115.86 305.41,1126.86 305.6,1126.86 313.69,1134.95 313.69,1146.61 U3.33@315.63,1148.54 ; R154.1@2312.99,170 v1(2312.99,187.99)
  Top Layer w6: v1(111,930) 154,930 R49.2@183,959 ; v1(2248,154) 2270.99,154 R154.2@2287.01,170
  Top Layer w10: R154.2@2287.01,170 R153.2@2287,198.01
  Top Layer w40: v1@53,1090 53,1722 163,1832 767,1832 ; v1@79,861 79,654 257,476 325,476
  Top Layer w56: 354,322.63 354,680
  Top Layer w60: C38.1@325,666 325,476 325,351.63 354,322.63 395.35,281.27 395.35,149.65 403.35,149.65 491,62 ; v1@1376,62 1414.91,62 1414.91,103.91 R67.2@1449,103.91
  Signal Layer 1 w6: v1(111,930) 111,613 650,74 1224.55,74 1248.55,98 1571,98 1592,77 2074,77 2151,154 v1(2248,154)
  Signal Layer 2 w40: v1@61,1159 61,884 v1(79,866) v1@79,792
  Bottom Layer w4: 2249,193 2259,203 2297.98,203 v1(2312.99,187.99)
  Bottom Layer w20: 2107.05,197.05 J7.2@2169.74,197.05 2237.05,197.05 ; 2108.54,228.54 J7.4@2169.74,228.54 2233.54,228.54
  Bottom Layer w40: 711,1832 767,1832 ; 711,1841 711,1858.91 R69.2@740,1887.91 ; R69.2@740,1887.91 767,1860.91 767,1832 ; R69.2@740,1887.91 740,1859 767,1832
  other v1: 1358,43 1398,43 1425,51 1333,56 1380,62 1408,72 1351,75 2020,110 1990,125 2045,135 2015,140 2050,165 2020,170 2080,170 365,730 365,765 76,793 365,800 88,818 73,839 47,1090 59,1114 46,1139 58,1165 771,1824 724,1825 700,1842 748,1843
VDCDC2_B_LS2: C42.1 J7.14 R33.2 U4.A1 U4.B1 U4.C1 | length 280
  Top Layer w20: R33.2@2050,339.17 2053.17,339.17 v1(2100,386) 2075.05,386 2052,362.95 R33.2@2052,350.02
  Bottom Layer w20: v1(2100,386) 2090.57,376.57 v1(2070,376.57) 2070,381 2075.02,386.02 J7.14@2169.74,386.02
VDCDC3_A: C18.1 C19.1 C20.1 C21.1 J7.75 J7.77 L3.2 R17.2 R68.2 R141.1 R141.2 R142.1 U1.2 | length 2413.7
  Top Layer w4: U1.2@1305.33,1016.46 1307.27,1018.39 1307.27,1030.05 1315.36,1038.14 1327.74,1038.14 1332.55,1033.33 v1@1359.67,1033.33
  Bottom Layer w4: v1(1359,1033.33) 1447.32,1121.65 1447.32,1215.22 1458.1,1226 1563.05,1330.95 1607,1287 ; 1563,1331 1597,1365 1656,1365 R17.2@1679.35,1388.35
  Bottom Layer w6: 1607,1287 1743,1287 1758,1302 R141.1@1790.01,1302 ; R141.1@1788,1301.01 R142.1@1817,1301.01 ; R141.2@1790.01,1330 1790.01,1345.01 1807,1362 v1(1888,1362)
  Bottom Layer w22: v1(1888,1362) v1(1998,1362) ; v1(1889,1393.9) J7.77@1944.26,1393.9 ; J7.75@1944.26,1362.4 J7.77@1944.26,1393.9 ; v1(1995.1,1393.9) J7.77@1944.26,1393.9
  Bottom Layer w40: R68.2@1080,1887.91 1080,1804 1143,1741 1700,1741 1761,1680 1761,1390 1715,1344
  other v1: 1714,1313 1697,1334 1723,1345
VDCDC3_B: C43.1 C44.1 C45.1 C46.1 J7.38 J7.40 L6.2 R50.2 R147.1 R147.2 R149.2 U3.2 | length 3078.3
  Top Layer w4: U3.2@451.46,1189.88 468.88,1189.88 468.88,1188.81 495,1162.69 495,1082 525,1052 525,933 v1(547,911)
  Top Layer w6: v1(689,680) 689,534.03 754.03,469 1777,469 1792,454 2042,454 2135,547 2135,694 2152,711 2306,711 2318,723 2318,751 2310.01,758.99 R149.2@2294,758.99 R147.1@2294,833.01 ; 2252,802 2269.01,819.01 R147.2@2269.01,834
  Signal Layer 1 w6: v1(547,911) 689,769 v1(689,680)
  Bottom Layer w4: v1(547,911) R50.2@609.76,911
  Bottom Layer w20: v1(2114,764) v1(2226,764) ; v1(2115,795) v1(2226,795)
  other v1: 695,875 745,875 720,885
VDDR: C97.1 C98.1 J7.3 R34.2 R66.1 R67.1 R77.2 U9.2 | length 2322.2
  Top Layer w6: v1(571,768) 612,768 660,720 660,535 740,455 1165,455 1223,397 v1(1257,397)
  Top Layer w14: v1(1257,397) 1290.41,397 R77.2@1307.85,414.45
  Top Layer w30: R66.1@1575.09,203 v1(1630,203) v1@1655,203
  Top Layer w50: R67.1@1567.09,100 R66.1@1567.09,195
  Signal Layer 2 w30: v1@1655,203 v1(1630,203) 1332,203 1245,290 1245,385 ; 1245,385 1245,408 1257,420 v1(1257,397) 1245,385
  Bottom Layer w6: v1(571,768) R34.2@571,810.38
  Bottom Layer w12: C98.1@1296.48,409.45 1326.79,379.13 U9.2@1326.79,349.02
  Bottom Layer w30: v1(1630,203) 1655,203 1800,203 1825.54,228.54 J7.3@1944.26,228.54
  Bottom Layer w50: C97.1@1216.48,409.45 C98.1@1296.48,409.45
  other v1: 1658,203 1257,423
VDDR_HLF: C96.1 R77.1 R78.1 R79.2 U9.1 | length 264.4
  Top Layer w10: R77.1@1355.1,414.45 R79.2@1405.1,414.45
  Top Layer w12: 1289.65,349 R77.1@1355.1,414.45
  Top Layer w14: v1(1276,349) 1289.65,349
  Top Layer w20: R79.2@1405.1,414.45 R78.1@1439.39,414.45
  Bottom Layer w10: C96.1@1235.1,344.45 1239.67,349.02 U9.1@1307.11,349.02
VIO: R3.2 R4.2 R11.2 R12.2 R13.2 R14.2 R31.2 R32.2 R44.2 R45.2 R46.2 R47.2 R60.1 R68.1 R69.1 R70.1 R71.1 R72.1 R82.1 R84.1 R87.1 R88.1 R89.1 R90.1 R91.1 R92.1 R93.2 R94.1 R95.1 R96.1 R97.2 R98.2 R99.1 R100.1 R101.2 R156.1 | length 9907.1
  Top Layer w10: R89.1@1349,1797.99 1349,1905.51 v1(1412.74,1969.26) R87.1@1448.79,1969.26
  Signal Layer 1 w14: v1(2270.74,75.74) 2363.74,75.74 2406,118 2406,155 2444,193 v1(2444,459)
  Signal Layer 2 w14: v1(1627,117) 1695,49 2244,49 v1(2270.74,75.74)
  Bottom Layer w14: 145,424 205.32,484.32 205.32,541.32 251.24,587.24 R97.2@282,587.24 318.38,623.63 R98.2@755.63,623.63 ; R98.2@758,626 847,626 R99.1@849,628 850,629 850,665 895,710 925,710 944,691 R100.1@944,629 R101.2@1041.5,629 ; R156.1@829.92,2623.62 901.62,2623.62 927.24,2598 1010,2598 1090.65,2517.35 R60.1@1090.65,2435 ; 1025.17,2324.83 R93.2@1090.38,2324.83 ; 1055,3107 1135,3027 R92.1@1139.09,3027 ; 1291.48,90.93 1299.68,99.13 1542.87,99.13 1560.75,117 v1(1627,117) ; 1379.91,2002.09 v1(1412.74,1969.26) ; v1(2270.74,75.74) R90.1@2270.74,117.21 ; R88.1@2444,421.24 v1(2444,459)
  Bottom Layer w16: R68.1@1080,2002.09 1379.91,2002.09
  Bottom Layer w20: 1010,2598 1010,3065 1090,3145 R72.1@1136.59,3145 ; 1025,2004.09 1025,2408 1052,2435 R60.1@1090.65,2435 ; 1149.17,140.83 R13.2@1149.17,650.55
  Bottom Layer w24: R45.2@91.38,1325 R46.2@91.38,1275 R47.2@91.38,1225 R32.2@91.38,1175 R31.2@91.38,1125 R44.2@91.38,1075 83,1075 43,1035 43,526 145,424 181,388 288.63,388 405,271.63 405,199 489,115 1123.35,115 1149.17,140.83 1215,75 1275.55,75 1291.48,90.93 R82.1@1291.48,140.83 ; 829.25,115.75 R84.1@829.25,377.09 ; R12.2@1116.35,661.38 R13.2@1160,661.38 R14.2@1210,661.38 R4.2@1260,661.38 R3.2@1310,661.38 R11.2@1360,661.38
  Bottom Layer w30: 58,1361.62 R45.2@93,1326.62
  Bottom Layer w34: 58,1361.62 58,1439
  Bottom Layer w42: 58,1439 58,1569
  Bottom Layer w46: 58,1569 58,1643
  Bottom Layer w50: 58,1643 417.09,2002.09 R69.1@740,2002.09 R70.1@855,2002.09 R71.1@970,2002.09 R68.1@1080,2002.09
VLDO1A_1V8: C23.1 J7.53 R40.2 U1.20 | length 2174.5
  Top Layer w6: v1(447,768) 447,751 498,700 v1(627,700)
  Signal Layer 2 w20: 1785,1050 v1(1809,1026)
  Signal Layer 2 w30: 949,825 920,854 920,881 ; 954,820 v1(971,820) ; v1(999,817) 984,817 v1(957,844) 920,881 ; 1785,1050 1633,1050 1519,1164 1133,1164 1105,1192 1047,1192 920,1065 920,881
  Bottom Layer w6: v1(447,768) R40.2@447,810.38 ; v1(627,700) 785,700 929,844 v1(957,844)
  Bottom Layer w20: v1(1809,1026) 1819.06,1015.94 J7.53@1944.26,1015.94
VLDO2A_3V3: C24.1 C92.1 J7.55 R70.2 R80.1 R136.2 U1.18 U9.10 | length 4883.6
  Top Layer w40: v1(1850,1048) v1(1878,1048) 2023,1048 2070,1095 2124,1095 2276.91,1247.91 R136.2@2395,1247.91
  Signal Layer 1 w10: v1@1248,139 1266,121 v1(1346.65,121)
  Signal Layer 1 w40: v1(1221,140) v1(1248,140)
  Signal Layer 1 w44: 890,158.85 925.73,123.13 1204.13,123.13 v1(1221,140)
  Signal Layer 1 w54: v1(880,348) 880,170 890,160
  Signal Layer 2 w30: v1@966,935 968,935 v1(982,921) 972,911 v1(957,911) 957,945 v1@966,936 ; 984,912 1043.35,971.35 1043.35,1000.35 1168,1125 1503.37,1125 1654.37,974 1822.18,974 1878,1029.82 v1(1878,1048) v1(1850,1048) 1850,1005
  Signal Layer 2 w50: v1@777,794 v1(777,730) 777,728 935,570 935,435 881,381
  Signal Layer 2 w54: 881,314 881,381
  Bottom Layer w10: C92.1@1229.45,199.45 1268.78,238.78 U9.10@1307.11,238.78 ; v1(1346.65,121) R80.1@1366.48,140.83
  Bottom Layer w20: C92.1@1221,179.52 v1(1221,140) v1(1248,140) ; C92.1@1221.48,199.45 1221.48,166.52 v1(1248,140) ; C92.1@1233,181 1248,166 v1(1248,140) ; 1835,1048 v1(1850,1048) v1(1878,1048) J7.55@1945,1048
  Bottom Layer w40: R70.2@855,1887.91 855,1801 930,1726 930,1115.58 877,1062.58 877,986 926.5,936.5
  Bottom Layer w50: 776,740.5 776,786 920,930 ; 925,926 973,926
  other v1: 865,324 897,324 777,762 777,795 964,941
VLED: Q2.2 R117.2 R119.2 R120.2 R121.2 R122.2 R129.2 R130.2 R131.2 R135.1 R136.1 | length 3248.7
  Top Layer w10: R122.2@2268.62,2385 v1(2324,2385) ; R117.2@2276.02,975 v1(2333.87,975) ; R130.2@2282.24,2895 v1(2321,2895) ; R129.2@2284.67,2638.58 v1(2324.58,2638.58) ; R131.2@2285.87,3163.52 v1@2321.52,3163.52 ; R119.2@2288.62,1633 v1(2325,1633) ; R121.2@2288.62,2125 v1(2323,2125) ; R120.2@2292.62,1875 v1(2325,1875) ; v1(2334,631) 2369.16,631 Q2.2@2422.4,577.76
  Top Layer w50: 2380,1567 2402.09,1544.91 R135.1@2402.09,1455 R136.1@2402.09,1369.17
  Signal Layer 2 w50: 2322,2136.37 2322,1628 v1(2373,1577) 2401,1549 2401,1370.24 2333.87,1303.12 v1@2333.87,631.13 ; 2322,2137.36 2322,2388.61 2312.13,2398.48 2312.13,2431.52 2322,2441.39 v1(2322,3164)
  other v1: 2393,1518 2410,1541 2379,1549 2400,1568
VREFCA_DDR: C95.1 J7.23 U9.6 | length 728.7
  Signal Layer 2 w16: v1(1414,247) 1547,247 1843.5,543.5 v1(1873.5,543.5)
  Bottom Layer w10: U9.6@1385.85,238.78 1405.78,238.78 v1(1414,247) 1440.3,247 C95.1@1452.85,234.45
  Bottom Layer w16: v1(1873.5,543.5) J7.23@1944.26,543.5
VREG5_8A: C80.1 R75.2 U7.17 | length 217.4
  Top Layer w10: R75.2@1156.38,3030 1181.06,3054.69 1241.4,3054.69 C80.1@1286.71,3100 ; C80.1@1292.18,3105.47 U7.17@1350.26,3105.47
VREG5_12A: C63.1 R64.2 U5.17 | length 169.6
  Top Layer w10: R64.2@1160.65,2305 1185.33,2329.68 1209.18,2329.68 C63.1@1246.5,2367 ; C63.1@1251.24,2380.47 U5.17@1309.31,2380.47
VRTC_A: C25.1 J7.28 R10.1 U1.16 | length 1537.7
  Top Layer w7.8: 1127.13,912.13 U1.16@1153.76,912.13
  Top Layer w16: 1105,912.13 1127.13,912.13
  Signal Layer 2 w16: v1(1118,912) 1118,731 1229,620 1491,620 1503,632 2013.03,632 2015.21,629.82 2034.16,629.82 2036.33,632 2200,632 v1(2225.5,606.5)
  Bottom Layer w10: v1(1410,620) R10.1@1410,661.38
  Bottom Layer w14: C25.1@1118.13,872.13 v1@1118.13,912.13
  Bottom Layer w20: J7.28@2169.74,606.5 v1(2225.5,606.5)
VRTC_B: C50.1 J7.26 R43.1 U3.16 | length 3386.9
  Top Layer w7.6: U3.16@347.13,1341.46 v1(347.13,1360)
  Signal Layer 1 w14: v1(347.13,1360) 347.13,1380.13 469,1502 829,1502 909,1422 909,843 v1(964,788)
  Signal Layer 2 w14: v1(235,1010) 235,1076
  Signal Layer 2 w16: v1(964,788) 1024,728 1087,728 1218,597 1753,597 1765,609 2003.5,609 2005.68,606.82 2043.68,606.82 2045.86,609 2134,609 2168,575 v1(2228,575)
  Signal Layer 2 w18: 235,1076 265,1106
  Signal Layer 2 w20: 265,1106 265,1277.87 v1(347.13,1360)
  Bottom Layer w10: R43.1@91.38,1025 117.38,999 224,999 v1(235,1010)
  Bottom Layer w20: C50.1@315,1415 347.13,1382.87 v1(347.13,1360) ; J7.26@2169.74,575 v1(2228,575)
VSYS: C8.1 C12.1 C13.1 C33.1 C34.1 C35.1 C52.1 C53.1 C54.1 C55.1 C56.1 C57.1 C69.1 C70.1 C71.1 C72.1 C73.1 C74.1 C82.1 C83.1 C84.1 C114.1 C115.1 D1.4 J1.1 J2.1 R1.1 R5.2 R6.2 R8.2 R18.2 R19.2 R20.2 R21.2 R30.1 R36.2 R37.2 R38.2 R51.2 R52.2 R53.2 R135.2 U1.5 U1.6 U1.19 U1.36 U3.5 U3.6 U3.19 U3.36 U5.2 U5.11 U7.2 U7.11 U8.7 U8.8 | length 1843.7
  Top Layer w7: C114.1@1071.62,864.88 U1.19@1153.76,864.88 ; U1.36@1346.67,927.87 1383.87,927.87 1416.33,960.33 C13.1@1416.33,974.96 ; C13.1@1430.96,974.96 C13.1@1440,974.96
  Top Layer w14: R52.2@91.38,960 89.13,957.75 89.13,918.69 102.81,905 v1(220,905)
  Top Layer w20: C8.1@1229.96,1110 1250,1089.96 1250,1050 ; 1250.22,1016.46 1250.22,1049.78
  Top Layer w24: 1250.22,1030 1250.22,1049.78
  Top Layer w40: C8.1@1229.96,1110 C12.1@1280.04,1110
  Bottom Layer w7: R8.2@1041.38,1025 1044.38,1022 1048,1022 1052,1018 R5.2@1052,955.62
  Bottom Layer w10: R18.2@973,1239.62 1025.38,1292 v1(1046,1292) ; v1(1535,1013) 1588,1013 1602.62,1027.62 R21.2@1602.62,1053 ; v1(1603,1418) 1603,1440.73 1622.27,1460 1651.97,1460 R20.2@1683.62,1428.35
  Bottom Layer w14: v1(432,991) 413,1010 R30.1@413,1040.38 435.38,1040.38 v1(440,1045) ; v1(557,937) 577,957 648,957 660,945 R53.2@660,920.24 ; v1(1660,835) 1680,835 1700,815 1700,728.41 1666.35,694.76 R19.2@1665,694.76
  Bottom Layer w20: R37.2@215,1628.62 215,1700 235,1720 v1(316,1720) 335,1701 R36.2@335,1628.62 R38.2@375,1628.62 R51.2@415,1628.62 ; v1(1031,879) 1035,879 1041.38,885.38 R5.2@1041.38,945 ; R1.1@1453.62,975 1488,975 v1(1511,998)
  other v1: 547,385 562,406 551,433 470,435 515,435 585,435 625,435 968,879 994,881 1512,967 1536,982 400,995 1470,1009 440,1018 1496,1019 600,1155 600,1185 1309,1215 1270,1217 600,1220 1244,1226 1291,1235 1315,1248 1229,1249 1264,1249 552,1250 585,1250 1291,1267 600,1275 600,1315 600,1350 2240,1420 2320,1430 2330,1460 280,1467.3 2320,1490 320,1520 2235,1520 2330,1520 2320,1555 2235,1565 675,1625 725,1625 775,1625 825,1625 875,1625 650,1650 700,1650 750,1650 800,1650 850,1650 625,1675 675,1675 725,1675 775,1675 825,1675 875,1675 335,1699 500,2100 550,2100 600,2100 650,2100 700,2100 750,2100 800,2100 850,2100 900,2100 950,2100 525,2125 575,2125 625,2125 675,2125 725,2125 775,2125 825,2125 875,2125 925,2125 1370,2125 1345,2135 500,2150 550,2150 600,2150 650,2150 700,2150 750,2150 800,2150 850,2150 900,2150 950,2150 1328,2160 1328,2195 1325,2610 1326,2643 1325,2670 1335,2700 1370,2700 1470,2820 1375,2825 1425,2825 1400,2850 1450,2850 1375,2875 1425,2875 1470,2874.88 1450,2900 1425,2925 1450,2955 1425,2975 1370,2990 1365,3265 1455,3330 1425,3350 1450,3375 1363,3395 1405,3395 1365,3425 1405,3425 1450,3425 1375,3450 1425,3450
VTT: C85.1 C86.1 C87.1 J7.19 J7.21 R78.2 R81.2 U9.3 | length 1132.1
  Bottom Layer w4: 1734.87,384.87 1778.87,384.87 1854,460 1854,495
  Bottom Layer w6: R81.2@1500.1,347.26 1531.26,347.26 1544,360 1710,360 1734.87,384.87
  Bottom Layer w10: U9.3@1346.48,349.02 1346.48,374.45 C85.1@1381.48,409.45
  Bottom Layer w50: C85.1@1381.48,409.45 C86.1@1461.48,409.45 C87.1@1541.48,409.45 ; C87.1@1547.03,409 1677,409 1763,495 1973,495
  other v1: 1648,396 1615.96,400 1635,422
pads on no net: FID1.1 FID2.1 FID3.1 H1.1 H2.1 H3.0 H4.0 J1.MH-1 J2.MH1 J2.MH2 J5.MH1 J5.MH2 J6.MH1 J6.MH2 J7.43 J7.93 J7.95 J7.MH-1 J7.MH-2 U5. U7. U8.9@697.91,307.09 U8.9@733.35,307.09 U9.11@1286.24,284.05 U9.11@1286.24,303.74 U9.11@1321.67,293.9 U9.11@1371.28,293.9 U9.11@1406.71,284.05 U9.11@1406.71,303.74

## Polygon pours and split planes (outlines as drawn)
GND on Top Layer "TOP_LAYER_GND_P168" (solid, remove dead copper, pour order 168): 260,1455 260,1506 117,1506 117,1411 221,1411
GND on Top Layer "TOP_LAYER_GND_P160" (solid, remove dead copper, pour order 160): 1124,1168.24 1124,1121 1124,1084.02 1170.5,1065.5 1203.71,1052.27 1217,1034 1217,983 1199,983 1199,1033.27 1185.89,1044 1104,1044 1050,1044 1050,1168.24
NetL1_1 on Top Layer "TOP_LAYER_NETL1_1_P158" (solid, remove dead copper, pour order 158): 1117.61,1255 1113.72,1251.11 1113.72,1195 1113.72,1088.5 1215,1045 1218,1000 1235.01,1000 1237,1046.42 1203.21,1080.21 1203.21,1147 1203.21,1248.17 1196.38,1255
GND on Top Layer "TOP_LAYER_GND_P150" (solid, remove dead copper, pour order 150): 1387,1272 1387,1092 1387,1086 1330.5,1063.5 1284,1042 1284,1032 1284,983 1296,983 1296,1029 1314.53,1044.16 1399.16,1044.16 1455,1044.16 1455,1272
VCC_1or2A on Top Layer "TOP_LAYER_VCC_1OR2A_P146" (solid, remove dead copper, pour order 146): 1425,157.8 1426.77,159.57 1505,159.57 1520,174.57 1520,237 1533,250 1820,250 1830,260 1830,305 1820,315 1495,315 1427.26,247.26 1427.26,225
VDCDC2_B_LS2 on Top Layer "TOP_LAYER_VDCDC2_B_LS2_P144" (solid, remove dead copper, pour order 144): 1905,375 1905,288 1914,279 2063,279 2091,307 2091,358 2010,358 1993,375
VDCDC2_B on Top Layer "TOP_LAYER_VDCDC2_B_P142" (solid, remove dead copper, pour order 142): 1907,277 1907,255 1923,239 1923,118 1940,101 2045,101 2045,106 2110,171 2110,252 2085,277
VDCDC3_B on Top Layer "TOP_LAYER_VDCDC3_B_P138" (solid, remove dead copper, pour order 138): 1785,480 1800,465 2035,465 2120,550 2120,745.71 2124.29,750 2250,750 2260,760 2260,800 2250,810 2080,810 2045,775 2045,585 1985,525 1845,525 1825,545 1785,545
VDCDC3_B on Top Layer "TOP_LAYER_VDCDC3_B_P136" (solid, remove dead copper, pour order 136): 620,915 620,840 705,755 705,535 760,480 1550,480 1785,480 1785,545 1490,545 830,545 774,601 774,906.76 765.76,915
GND on Top Layer "TOP_LAYER_GND_P134" (solid, remove dead copper, pour order 134): 770,985 770,880 780,870 780,640 870,550 1695,550 1710,565 2010,565 2040,595 2040,700 2025,715 1787,715 1687,615 1635,615 975,615 855,735 855,959.61 829.61,985
VDCDC1_B on Top Layer "TOP_LAYER_VDCDC1_B_P132" (solid, remove dead copper, pour order 132): 810,1115 810,1075 855,1030 855,745 980,620 1630,620 1760,750 2020,750 2035,765 2035,830 2020,845 1845,845 1732,845 1587,700 1033,700 945,788 945,1045 875,1115
GND on Top Layer "TOP_LAYER_GND_P130" (solid, remove dead copper, pour order 130): 1670,2068 1670,2038.54 1685,2023.54 1685,1951.81 1697.13,1951.81 1697.13,1918.19 1685,1918.19 1681,1914.19 1681,1775 1688,1768 1690,1770 1770,1770 1770,1755 1730,1715 1626,1715 1626,2064 1630,2068
GND on Top Layer "TOP_LAYER_GND_P128" (solid, remove dead copper, pour order 128): 1725,1725 1770,1770 1839,1770 1855,1786 2000,1786 2017,1769 2017,1738 2005,1726 1854,1726 1778,1650 1714,1650 1709,1655 1708,1655 1708,1718 1715,1725
VDCDC2_A on Top Layer "TOP_LAYER_VDCDC2_A_P126" (solid, remove dead copper, pour order 126): 1708,1184 1731,1194 1807,1194 1862,1249 1898,1249 2022,1249 2034,1237 2034,1197 2023,1186 1889,1186 1805,1102 1730.55,1102 1708,1143
GND on Top Layer "TOP_LAYER_GND_P124" (solid, remove dead copper, pour order 124): 1703,1270 1714,1281 1774,1281 1809,1316 1893,1316 2019,1316 2035,1300 2035,1271 2019,1255 1859,1255 1807,1203 1706.85,1203 1703,1210
VDCDC3_A on Top Layer "TOP_LAYER_VDCDC3_A_P122" (solid, remove dead copper, pour order 122): 1691,1365 1702,1376 1720,1394 1737,1411 1881,1411 2000,1411 2020,1391 2020,1366 2000,1346 1843,1346 1782,1285 1702,1285 1691,1295
GND on Top Layer "TOP_LAYER_GND_P120" (solid, remove dead copper, pour order 120): 2003.38,1622 2039,1594.76 2039,1556.99 1975.29,1511 1574,1511 1521.5,1458.5 1171,1458.5 1171,1559 1474,1559 1681,1559 1732,1607 1824,1607 1839,1622
VDCDC1_A on Top Layer "TOP_LAYER_VDCDC1_A_P118" (solid, remove dead copper, pour order 118): 2009.92,1536 2035,1516.82 2035,1457.6 2013,1440 1601,1440 1530,1369 1529,1370 1468,1370 1468,1447 1473,1452 1518,1452 1576,1510 1825,1510 1851,1536
VSYS on Top Layer "TOP_LAYER_VSYS_P102" (solid, remove dead copper, pour order 102): 371,1163 358,1163 358,1113 373,1098 373,1006 398,981 450,981 450,1098 402,1098 371,1129
NetL5_1 on Top Layer "TOP_LAYER_NETL5_1_P012" (solid, remove dead copper, pour order 12): 339,1163 339,1106.7 300,1067.7 300,991 294,985 294,910.59 381,910.59 381,990 370,1001 370,1101 354,1117 354,1163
